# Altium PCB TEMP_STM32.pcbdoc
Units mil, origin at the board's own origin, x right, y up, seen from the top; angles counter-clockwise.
Board outline 2892.2 x 2755.09 mil, 2 copper layers (Top Layer, Bottom Layer); 81 components, 62 nets, 281 pads, 162 vias.
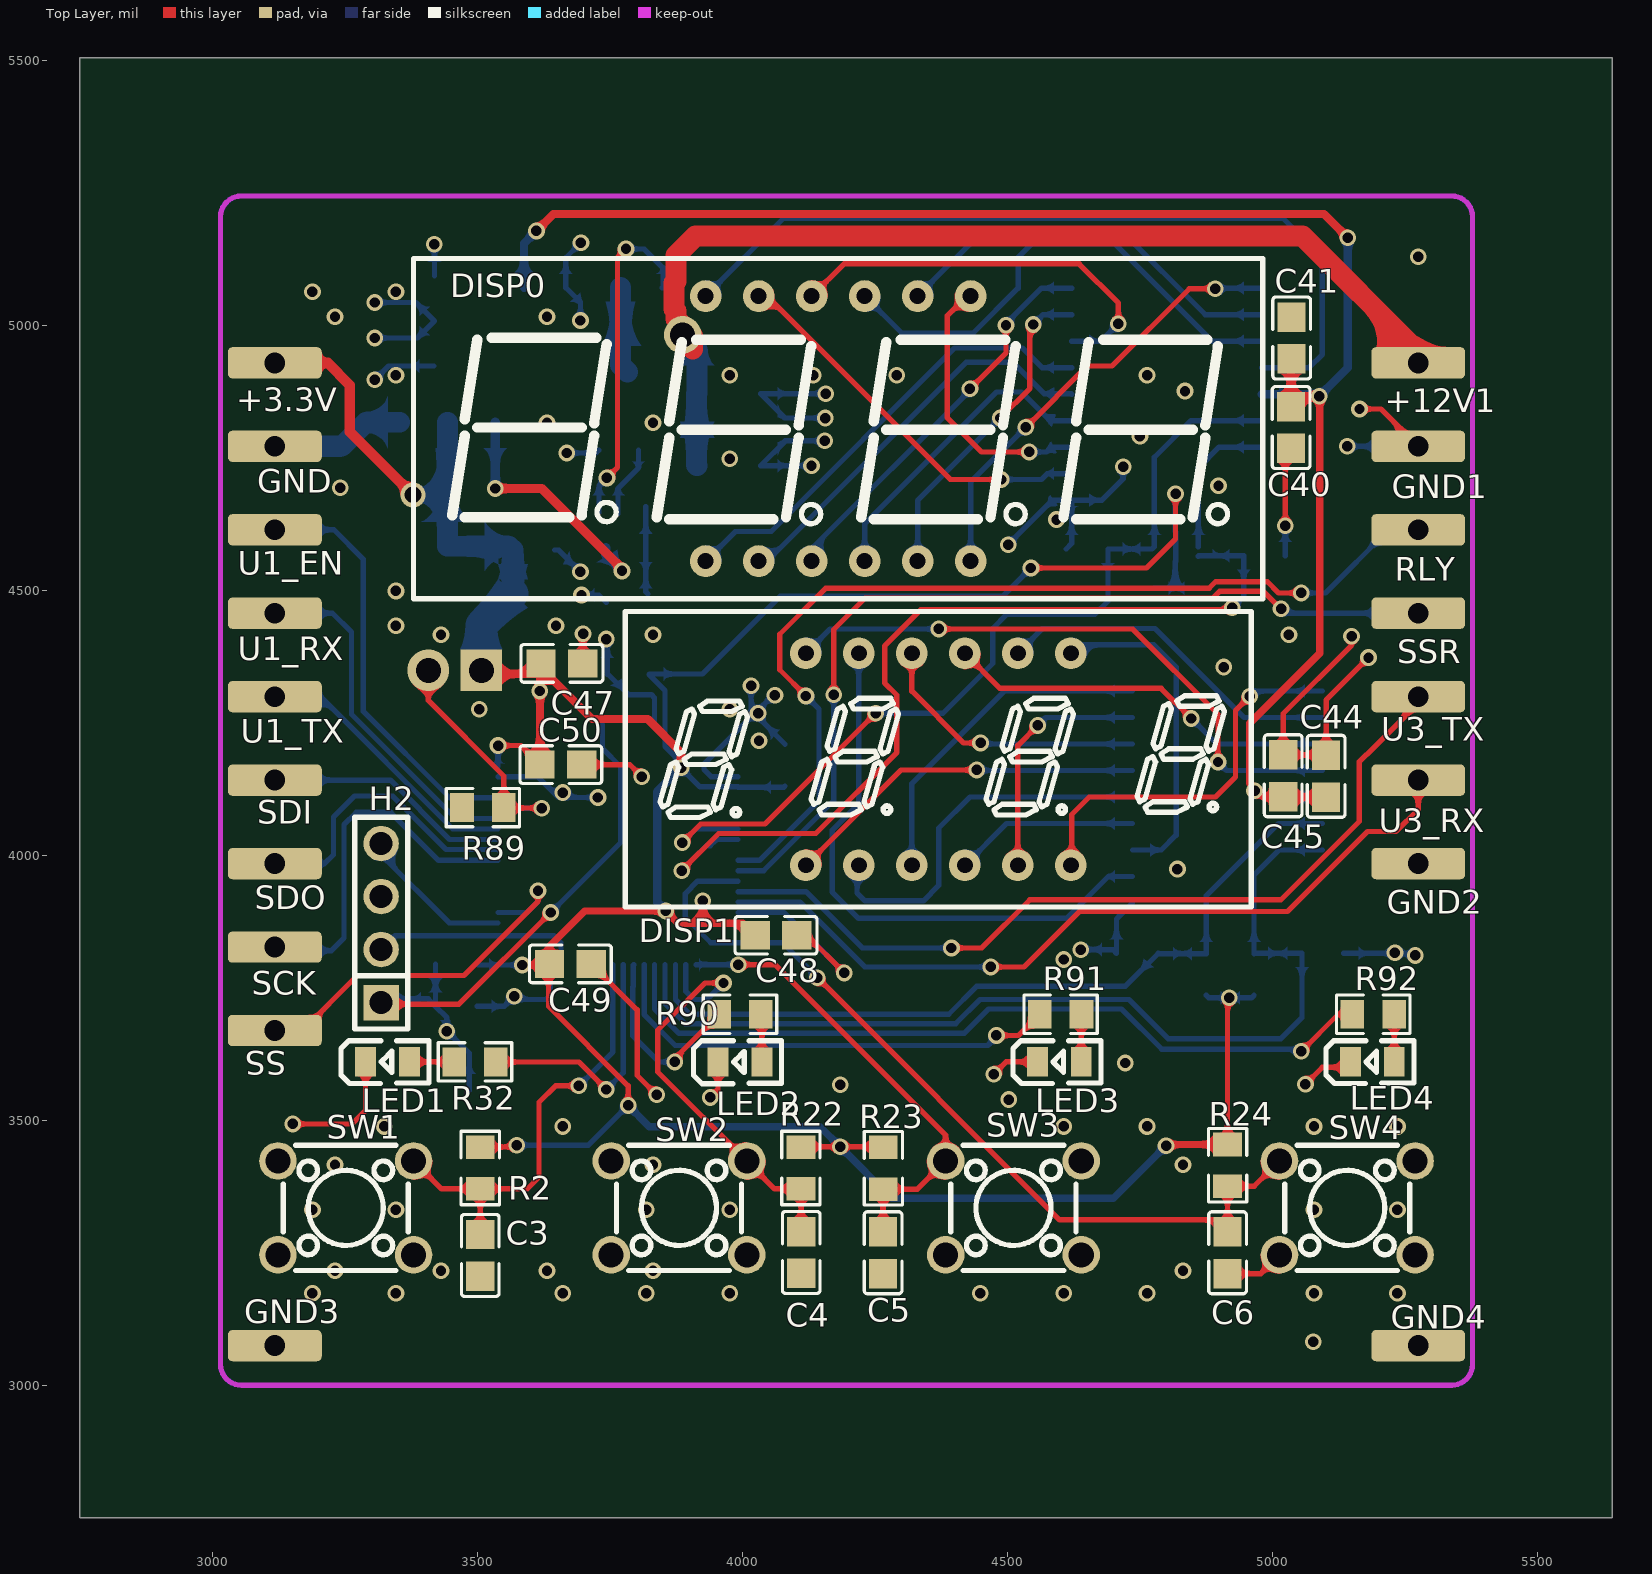
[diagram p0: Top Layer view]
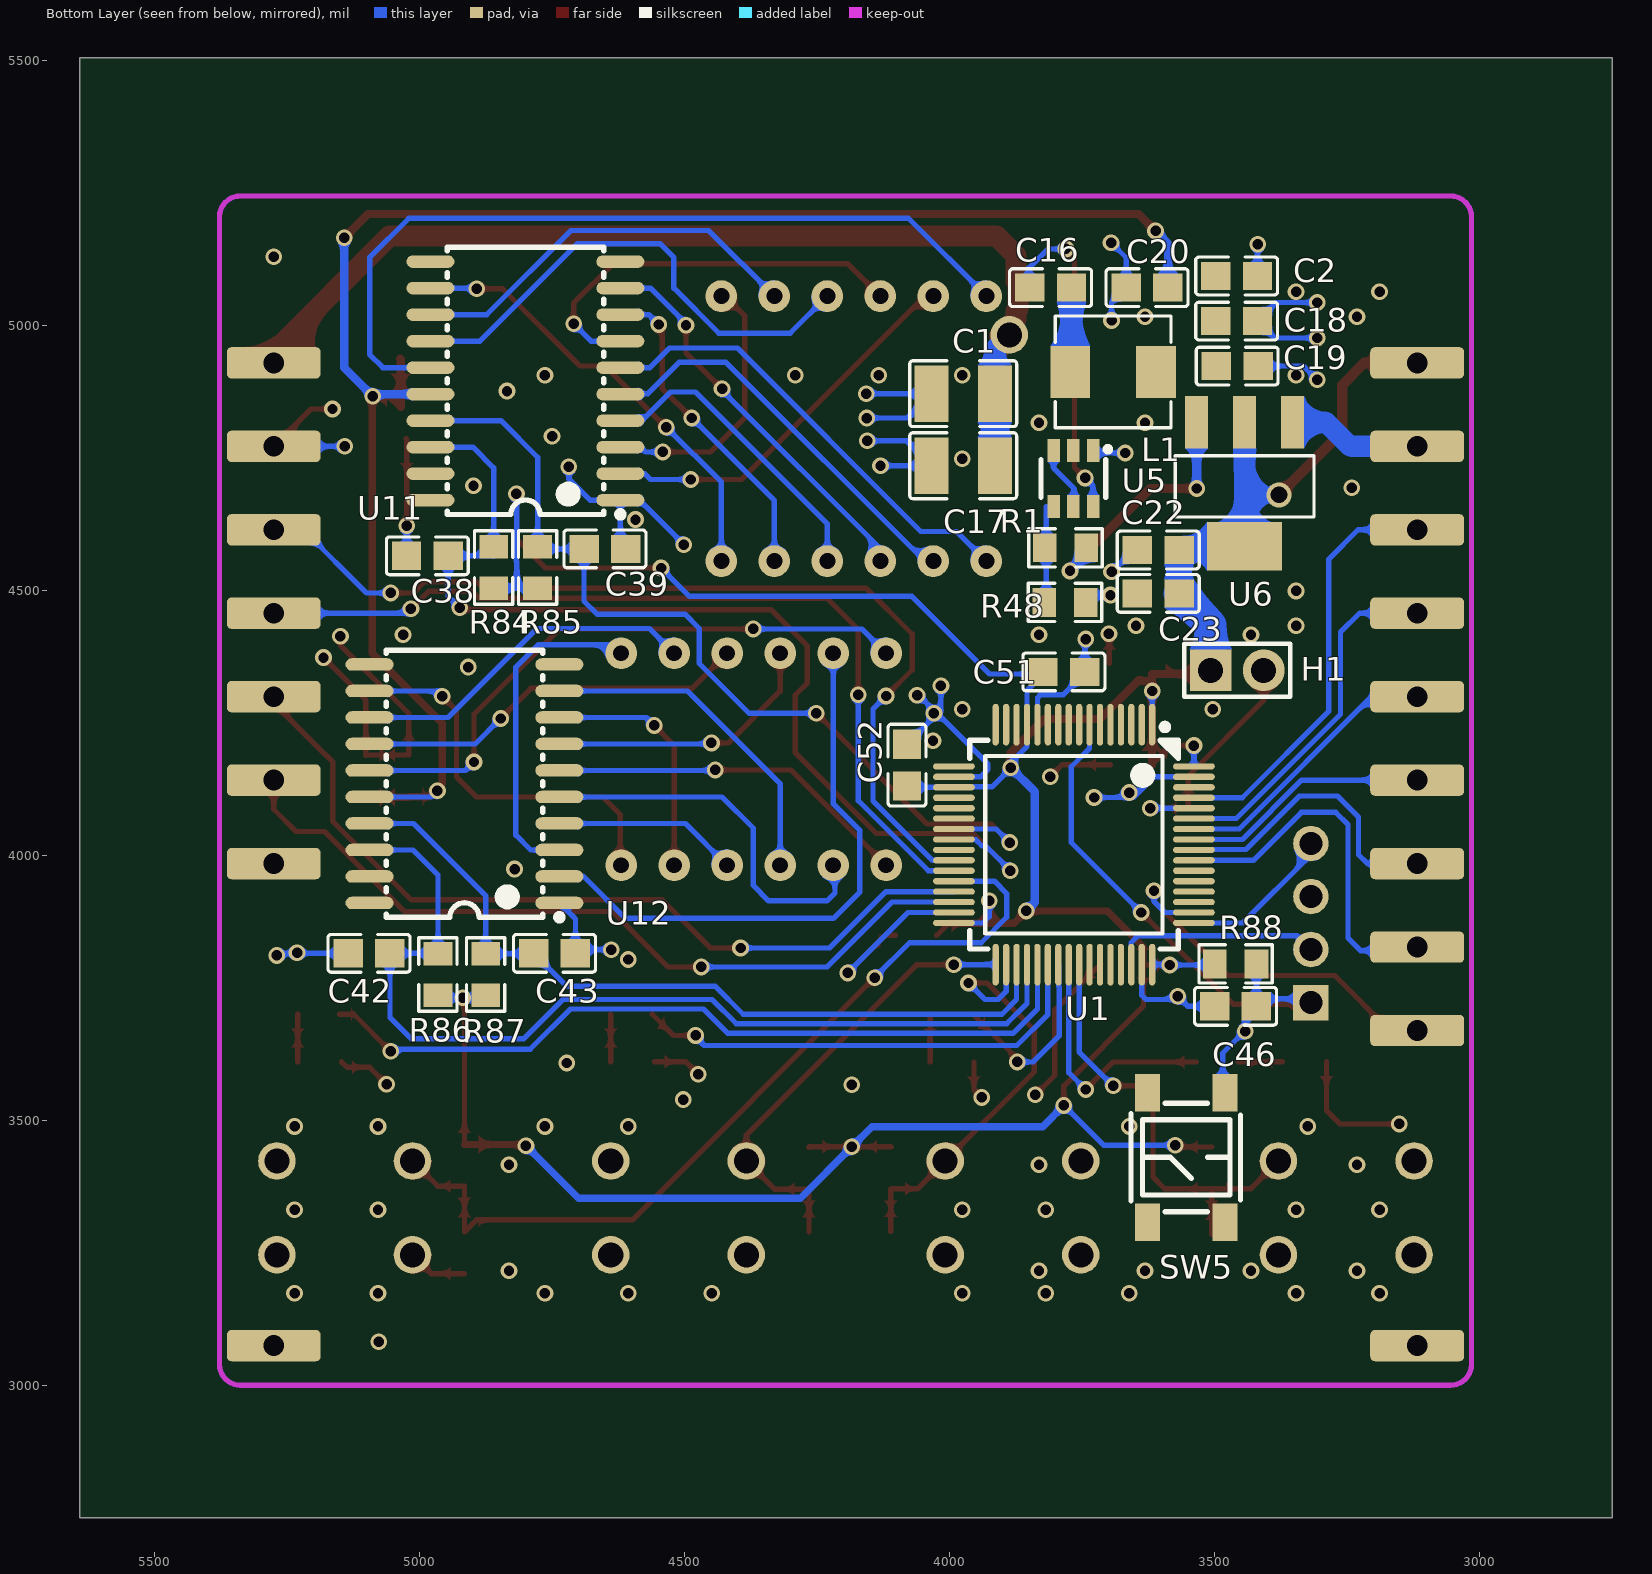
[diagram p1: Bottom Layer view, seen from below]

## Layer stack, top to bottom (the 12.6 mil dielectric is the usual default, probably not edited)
Top Layer: signal copper (thickness not stored)
Dielectric: dielectric 12.6, FR-4, Dk 4.8
Bottom Layer: signal copper (thickness not stored)

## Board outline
5642.2,2750 2750,2750 2750,5505.09 5642.2,5505.09

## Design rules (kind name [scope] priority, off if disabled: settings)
BoardOutlineClearance copperThickness1oz [All] p0: genericclearance=10 ignorepadtopadclearanceinfootprint=FALSE except(0: Arc-SplitContinuation Track-SplitContinuation SMDPad-SplitContinuation THPad-SplitContinuation Via-SplitContinuation Fill-SplitContinuation Poly-SplitContinuation Region-SplitContinuation Text-SplitContinuation; 8: Track-CutoutEdge SMDPad-CutoutEdge THPad-CutoutEdge Via-CutoutEdge Region-CutoutEdge; 11.8: Track-OutlineEdge SMDPad-OutlineEdge THPad-OutlineEdge Via-OutlineEdge Fill-OutlineEdge Region-OutlineEdge Poly-OutlineEdge Text-OutlineEdge Fill-CutoutEdge)
BoardOutlineClearance copperThickness2oz [All] p0: genericclearance=10 ignorepadtopadclearanceinfootprint=FALSE except(0: Arc-SplitContinuation Track-SplitContinuation SMDPad-SplitContinuation THPad-SplitContinuation Via-SplitContinuation Fill-SplitContinuation Poly-SplitContinuation Region-SplitContinuation Text-SplitContinuation; 6: Track-CutoutEdge SMDPad-CutoutEdge THPad-CutoutEdge Via-CutoutEdge Region-CutoutEdge; 11.8: Track-OutlineEdge SMDPad-OutlineEdge THPad-OutlineEdge Via-OutlineEdge Fill-OutlineEdge Region-OutlineEdge Poly-OutlineEdge Text-OutlineEdge Fill-CutoutEdge)
Clearance copperThickness1oz [(InNet('+12V') OR InNet('GND') OR InNet('+5V') OR InNet('$1N5723') OR InNet('$1N5726') OR InNet('+3.3V') OR InNet('CLK1') OR InNet('DIO1') OR InNet('RST') OR InNet('SEG_E2') OR InNet('SEG_D2') OR InNet('SEG_H2') OR InNet('SEG_C2') OR InNet('SEG_G2') OR InNet('DIG_8') OR InNet('SEG_B2') OR InNet('DIG_7') OR InNet('DIG_6') OR InNet('SEG_F2') OR InNet('SEG_A2') OR InNet('DIG_5') OR InNet('DIG_1') OR InNet('DIG_2') OR InNet('DIG_3') OR InNet('DIG_4') OR InNet('$1N5728') OR InNet('SWCLK') OR InNet('SWDIO') OR InNet('SEG_A1') OR InNet('SEG_B1') OR InNet('SEG_C1') OR InNet('SEG_D1') OR InNet('SEG_E1') OR InNet('SEG_F1') OR InNet('SEG_G1') OR InNet('SEG_H1') OR InNet('$1N10529') OR InNet('$1N10623') OR InNet('$1N10717') OR InNet('$1N10811') OR InNet('CLK2') OR InNet('DIO2') OR InNet('BOOT0') OR InNet('M_SCK') OR InNet('M_SS') OR InNet('U1_RX') OR InNet('U1_TX') OR InNet('U3_RX') OR InNet('U3_TX') OR InNet('M_SDI') OR InNet('M_SDO') OR InNet('LD3') OR InNet('LD2') OR InNet('LD1') OR InNet('LD4') OR InNet('SSR') OR InNet('RLY') OR InNet('U1_EN') OR InNet('SW1') OR InNet('SW2') OR InNet('SW3') OR InNet('SW4'))] p1: gap=7 ignorepadtopadclearanceinfootprint=FALSE except(7.9: SMDPad-SMDPad; 8: Track-Track Track-SMDPad Track-Via SMDPad-Via THPad-Via SMDPad-Fill THPad-Fill Via-Fill Fill-Fill Track-Region SMDPad-Region THPad-Region Via-Region Region-Region Track-Poly SMDPad-Poly THPad-Poly Via-Poly Fill-Poly Region-Poly Poly-Poly Track-Text SMDPad-Text THPad-Text Via-Text Fill-Text Region-Text Poly-Text Text-Text Track-Hole SMDPad-Hole THPad-Hole Via-Hole Fill-Hole Region-Hole Poly-Hole Text-Hole Sheet-Hole; 10: Track-THPad SMDPad-THPad THPad-THPad; 11.8: Track-Fill Fill-Region Track-Sheet SMDPad-Sheet THPad-Sheet Via-Sheet Fill-Sheet Region-Sheet Poly-Sheet Text-Sheet; 12: Via-Via)
Clearance copperThickness2oz [All] p1: gap=7 ignorepadtopadclearanceinfootprint=FALSE except(6: Track-SMDPad SMDPad-SMDPad Track-THPad SMDPad-THPad THPad-THPad Track-Via SMDPad-Via THPad-Via Via-Via SMDPad-Fill THPad-Fill Via-Fill Fill-Fill Track-Region SMDPad-Region THPad-Region Via-Region Region-Region Track-Poly SMDPad-Poly THPad-Poly Via-Poly Fill-Poly Region-Poly Poly-Poly Track-Text SMDPad-Text THPad-Text Via-Text Fill-Text Region-Text Poly-Text Text-Text; 6.9: Track-Hole SMDPad-Hole THPad-Hole Via-Hole Fill-Hole Region-Hole Poly-Hole Text-Hole Sheet-Hole; 8: Track-Track; 11.8: Track-Fill Fill-Region Track-Sheet SMDPad-Sheet THPad-Sheet Via-Sheet Fill-Sheet Region-Sheet Poly-Sheet Text-Sheet)
DiffPairsRouting differentialPair [All] p1: maxuncoupledlength=10 minlimit=5.9843 maxlimit=5.9843 mostfreqgap=5.9843 toplayer_minwidth=5 toplayer_prefwidth=10 toplayer_maxwidth=100 bottomlayer_minwidth=5 bottomlayer_prefwidth=10 bottomlayer_maxwidth=100
PasteMaskExpansion pasteMaskExpansion [All] p1: expansion=0
PlaneConnect innerPlane [All] p1: planeconnectstyle=Relief reliefexpansion=20 reliefentries=4 reliefconductorwidth=10 reliefairgap=10
PolygonConnect copperRegion [All] p1: connectstyle=Direct reliefentries=4 reliefconductorwidth=10 polygonreliefangle="90 Angle" airgapwidth=10
RoutingVias viaSize [All] p1: viastyle="Through Hole" holewidth=19.685 minholewidth=19.685 maxholewidth=393.7008 width=31.496 minwidth=19.685 maxwidth=393.7008
SolderMaskExpansion solderMaskExpansion [All] p1: useseparateexpansions=TRUE expansion=2.0079 expansionbottom=2.0079
Width copperThickness1oz [All] p1: maxlimit=100 minlimit=5 preferedwidth=10
Width copperThickness2oz [All] p1: maxlimit=100 minlimit=8 preferedwidth=10

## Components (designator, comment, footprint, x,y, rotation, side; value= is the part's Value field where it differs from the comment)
+3.3V "S_TM" S_FT 3118.36,4929.13 r90 top
+12V1 "S_TM" S_FT 5275.84,4929.13 r90 top
C1 "CS3225X7R106K500NRL" C1210 3975,4871 r180 bottom
C2 "GRM21BZ71A226ME15L" C0805 3459,5093 r0 bottom
C3 "CC0805KRX7R9BB104" C0805 3506,3245 r90 top
C4 "CC0805KRX7R9BB104" C0805 4111.63,3250.63 r90 top
C5 "CC0805KRX7R9BB104" C0805 4266,3250 r90 top
C6 "CC0805KRX7R9BB104" C0805 4916,3250 r90 top
C16 "CC0805KRX7R9BB104" C0805 3810,5071 r180 bottom
C17 "CS3225X7R106K500NRL" C1210 3975,4735 r180 bottom
C18 "GRM21BZ71A226ME15L" C0805 3459,5008 r0 bottom
C19 "GRM21BZ71A226ME15L" C0805 3458,4923 r0 bottom
C20 "CC0805KRX7R9BB104" C0805 3628,5071 r180 bottom
C22 "CC0805KRX7R9BB104" C0805 3607,4576 r180 bottom
C23 "GRM21BR61C106KE15L" C0805 3607,4494 r180 bottom
C38 "CC0805KRX7R9BB101" C0805 4986,4565 r180 bottom
C39 "CC0805KRX7R9BB101" C0805 4651,4578 r0 bottom
C40 "GRM21BZ71A226ME15L" C0805 5036,4807 r90 top
C41 "CC0805KRX7R9BB104" C0805 5037,4976 r270 top
C42 "CC0805KRX7R9BB101" C0805 5096,3815 r180 bottom
C43 "CC0805KRX7R9BB101" C0805 4746,3815 r0 bottom
C44 "GRM21BZ71A226ME15L" C0805 5102,4149 r270 top
C45 "CC0805KRX7R9BB104" C0805 5021,4150 r270 top
C46 "CC0805KRX7R9BB104" C0805 3461,3715 r180 bottom
C47 "CC0805KRX7R9BB101" C0805 3660,4362 r180 top
C48 "CC0805KRX7R9BB101" C0805 4064,3849 r180 top
C49 "CC0805KRX7R9BB101" C0805 3676,3795 r180 top
C50 "CC0805KRX7R9BB101" C0805 3658,4171 r180 top
C51 "CC0805KRX7R9BB101" C0805 3785,4346 r0 bottom
C52 "CC0805KRX7R9BB101" C0805 4081,4170 r270 bottom
DISP0 "FJ4401BH" LED-SEG-TH_12P-L40.4-W16.0-P2.54-S12.70-BL 4181.35,4805.12 r0 top locked
DISP1 "FJ3461BH" LED-SEG-TH_12P-L30.0-W13.7-P2.54-S10.16-BL 4370.33,4181.1 r0 top locked
GND "S_TM" S_FT 3118.36,4771.65 r270 top
GND1 "S_TM" S_FT 5275.84,4771.65 r90 top
GND2 "S_TM" S_FT 5275.84,3984.25 r90 top
GND3 "S_TM" S_FT 3118.36,3074.8 r270 top
GND4 "S_TM" S_FT 5275.84,3074.8 r90 top
H1 "PZ254V-11-02P" HDR-TH_2P-P2.54-V-M 3458,4349 r180 bottom
H2 "PZ254V-11-04P" HDR-TH_4P-P2.54-V-M 3319,3872 r90 top
L1 "RS0530-3R3MS" IND-SMD_L5.4-W5.2_RS0530 3692,4912 r0 bottom
LED1 "XL-2012SURC" LED0805-R-RD 3330.96,3610.24 r0 top
LED2 "XL-2012SURC" LED0805-R-RD 3996,3610 r0 top
LED3 "XL-2012SURC" LED0805-R-RD 4598.68,3610.24 r0 top
LED4 "XL-2012SURC" LED0805-R-RD 5189.23,3610.24 r0 top
R1 "RC0805FR-0756K2L" R0805 3782,4580 r0 bottom
R2 "RC0805FR-0710KL" R0805 3506,3410 r90 top
R22 "RC0805FR-0710KL" R0805 4111,3410 r90 top
R23 "RC0805FR-0710KL" R0805 4266.63,3409.37 r90 top
R24 "RC0805FR-0710KL" R0805 4916,3415 r90 top
R32 "RC0805FR-071KL" R0805 3496,3610 r0 top
R48 "RC0805FR-0710KL" R0805 3783,4477 r0 bottom
R84 "RC0805FR-0710KL" R0805 4861,4543 r270 bottom
R85 "RC0805FR-0710KL" R0805 4778,4543 r270 bottom
R86 "RC0805FR-0710KL" R0805 4966,3775 r270 bottom
R87 "RC0805FR-0710KL" R0805 4876,3775 r270 bottom
R88 "RC0805FR-0710KL" R0805 3461,3795 r0 bottom
R89 "RC0805FR-0710KL" R0805 3511,4090 r0 top
R90 "RC0805FR-071KL" R0805 3996,3700 r180 top
R91 "RC0805FR-071KL" R0805 4601,3700 r180 top
R92 "RC0805FR-071KL" R0805 5191,3700 r180 top
RLY "S_TM" S_FT 5275.84,4614.17 r90 top
SCK "S_TM" S_FT 3118.36,3826.77 r270 top
SDI "S_TM" S_FT 3118.36,4141.73 r90 top
SDO "S_TM" S_FT 3118.36,3984.25 r90 top
SS "S_TM" S_FT 3118.36,3669.29 r90 top
SSR "S_TM" S_FT 5275.84,4456.69 r90 top
SW1 "YTS1R0011FBT00" SW-TH_4P-L6.0-W6.0-P4.50-LS6.5 3252.22,3334.65 r0 top
SW2 "YTS1R0011FBT00" SW-TH_4P-L6.0-W6.0-P4.50-LS6.5 3881,3334.65 r0 top
SW3 "YTS1R0011FBT00" SW-TH_4P-L6.0-W6.0-P4.50-LS6.5 4512.06,3334.65 r0 top
SW4 "YTS1R0011FBT00" SW-TH_4P-L6.0-W6.0-P4.50-LS6.5 5141.98,3334.65 r0 top
SW5 "TSC005A1618A03" KEY-SMD_4P-L5.2-W5.2-P3.70-LS6.4 3554.04,3430 r270 bottom
U1 "STM32F103RCT6" LQFP-64_L10.0-W10.0-P0.50-LS12.0-BL 3766,4020 r0 bottom locked
U1_EN "S_TM" S_FT 3118.36,4614.17 r90 top
U1_RX "S_TM" S_FT 3118.36,4456.69 r90 top
U1_TX "S_TM" S_FT 3118.36,4299.21 r90 top
U3_RX "S_TM" S_FT 5275.84,4141.73 r90 top
U3_TX "S_TM" S_FT 5275.84,4299.21 r90 top
U5 "TPS562208DDCR" SOT-23-6_L2.9-W1.6-P0.95-LS2.8-BR 3767,4711 r90 bottom
U6 "AMS1117-3.3_C6068481" SOT-223-3_L6.5-W3.4-P2.30-LS7.0-BR 3444,4700 r90 bottom
U11 "TM1637" SOP-20_L12.8-W7.5-P1.27-LS10.4-BL 4801,4895 r90 bottom
U12 "TM1637" SOP-20_L12.8-W7.5-P1.27-LS10.4-BL 4916,4135 r90 bottom locked

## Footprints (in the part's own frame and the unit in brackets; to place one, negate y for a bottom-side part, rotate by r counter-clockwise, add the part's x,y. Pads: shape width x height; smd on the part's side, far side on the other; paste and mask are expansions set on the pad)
C0805 [mm]
  rect 1.41x1.35 smd: 1(-1,0) 2(1,0)
  silkscreen extent -1.96,-0.9 1.96,0.9
C1210 [mm]
  rect 1.635x2.7 smd: 1(-1.517,0) 2(1.517,0)
  silkscreen extent -2.56,-1.58 2.56,1.58
HDR-TH_2P-P2.54-V-M [mm]
  rect 2x2 hole 1.2: 1(-1.27,0)
  round 2 hole 1.2: 2(1.27,0)
  silkscreen extent -2.54,-1.27 2.54,1.27
HDR-TH_4P-P2.54-V-M [mm]
  rect 1.7x1.7 hole 1.1: 1(-3.81,0)
  round 1.7 hole 1.1: 2(-1.27,0) 3(1.27,0) 4(3.81,0)
  silkscreen extent -5.08,-1.27 5.08,1.27
IND-SMD_L5.4-W5.2_RS0530 [mm]
  rect 1.9x2.5 smd: 1(2.05,0) 2(-2.05,0)
  silkscreen extent -2.78,-2.68 2.78,2.68
KEY-SMD_4P-L5.2-W5.2-P3.70-LS6.4 [mm]
  rect 1.8x1.2 smd: 1(-3.1,1.85) 2(3.1,1.85) 3(-3.1,-1.85) 4(3.1,-1.85)
  silkscreen extent -2.6,-2.65 2.6,2.6
LED0805-R-RD [mm]
  rect 1x1.4 smd: 1(1.05,0) 2(-1.05,0)
  silkscreen extent -2.22,-1.04 1.99,1.01
LED-SEG-TH_12P-L30.0-W13.7-P2.54-S10.16-BL [mil]
  round 60 hole 30: 1(-250,-200) 2(-150,-200) 3(-50,-200) 4(50,-200) 5(150,-200) 6(250,-200) 7(250,200) 8(150,200) 9(50,200) 10(-50,200) 11(-150,200) 12(-250,200)
  silkscreen extent -591,-279 591,279
LED-SEG-TH_12P-L40.4-W16.0-P2.54-S12.70-BL [mil]
  round 60 hole 30: 1(-250,-250) 2(-150,-250) 3(-50,-250) 4(50,-250) 5(150,-250) 6(250,-250) 7(250,250) 8(150,250) 9(50,250) 10(-50,250) 11(-150,250) 12(-250,250)
  silkscreen extent -801,-321 801,321
LQFP-64_L10.0-W10.0-P0.50-LS12.0-BL [mm]
  oval 0.3x2 smd: 1(-3.75,-5.75) 2(-3.25,-5.75) 3(-2.75,-5.75) 4(-2.25,-5.75) 5(-1.75,-5.75) 6(-1.25,-5.75) 7(-0.75,-5.75) 8(-0.25,-5.75) 9(0.25,-5.75) 10(0.75,-5.75) 11(1.25,-5.75) 12(1.75,-5.75) 13(2.25,-5.75) 14(2.75,-5.75) 15(3.25,-5.75) 16(3.75,-5.75) 33(3.75,5.75) 34(3.25,5.75) 35(2.75,5.75) 36(2.25,5.75) 37(1.75,5.75) 38(1.25,5.75) 39(0.75,5.75) 40(0.25,5.75) 41(-0.25,5.75) 42(-0.75,5.75) 43(-1.25,5.75) 44(-1.75,5.75) 45(-2.25,5.75) 46(-2.75,5.75) 47(-3.25,5.75) 48(-3.75,5.75)
  oval 2x0.3 smd: 17(5.75,-3.75) 18(5.75,-3.25) 19(5.75,-2.75) 20(5.75,-2.25) 21(5.75,-1.75) 22(5.75,-1.25) 23(5.75,-0.75) 24(5.75,-0.25) 25(5.75,0.25) 26(5.75,0.75) 27(5.75,1.25) 28(5.75,1.75) 29(5.75,2.25) 30(5.75,2.75) 31(5.75,3.25) 32(5.75,3.75) 49(-5.75,3.75) 50(-5.75,3.25) 51(-5.75,2.75) 52(-5.75,2.25) 53(-5.75,1.75) 54(-5.75,1.25) 55(-5.75,0.75) 56(-5.75,0.25) 57(-5.75,-0.25) 58(-5.75,-0.75) 59(-5.75,-1.25) 60(-5.75,-1.75) 61(-5.75,-2.25) 62(-5.75,-2.75) 63(-5.75,-3.25) 64(-5.75,-3.75)
  silkscreen extent -5,-5.79 5,5
R0805 [mm]
  rect 1.133x1.377 smd: 1(-1,0) 2(1,0)
  silkscreen extent -1.76,-0.92 1.76,0.92
S_FT [mm]
  rrect30% 1.5x4.5 hole 1: 1(0,0)
SOP-20_L12.8-W7.5-P1.27-LS10.4-BL [mm]
  oval 0.6x2.3 smd: 1(-5.715,-4.55) 2(-4.445,-4.55) 3(-3.175,-4.55) 4(-1.905,-4.55) 5(-0.635,-4.55) 6(0.635,-4.55) 7(1.905,-4.55) 8(3.175,-4.55) 9(4.445,-4.55) 10(5.715,-4.55) 11(5.715,4.55) 12(4.445,4.55) 13(3.175,4.55) 14(1.905,4.55) 15(0.635,4.55) 16(-0.635,4.55) 17(-1.905,4.55) 18(-3.175,4.55) 19(-4.445,4.55) 20(-5.715,4.55)
  silkscreen extent -6.55,-4.7 6.4,3.75
SOT-23-6_L2.9-W1.6-P0.95-LS2.8-BR [mm]
  rect 1.1x0.6 smd: 1(1.35,-0.95) 2(1.35,0) 3(1.35,0.95) 4(-1.35,0.95) 5(-1.35,0) 6(-1.35,-0.95)
  silkscreen extent -0.9,-1.78 1.52,1.55
SOT-223-3_L6.5-W3.4-P2.30-LS7.0-BR [mm]
  rect 2.5x1.1 smd: 1(2.97,-2.3) 2(2.97,0) 3(2.97,2.3)
  rect 2.34x3.6 smd: 4(-2.97,0)
  silkscreen extent -1.57,-3.33 1.37,3.33
SW-TH_4P-L6.0-W6.0-P4.50-LS6.5 [mm]
  round 1.8 hole 1.2: 1(-3.25,2.25) 2(3.25,2.25) 3(-3.25,-2.25) 4(3.25,-2.25)
  silkscreen extent -3,-3 3,3

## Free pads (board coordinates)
  round 70.87 hole 47.24: 1(3888,4982)

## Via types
v1: diameter 31.5, hole 19.68, Top Layer to Bottom Layer, 113 vias
v2: diameter 31.5, hole 19.7, Top Layer to Bottom Layer, 48 vias
v3: diameter 47.24, hole 31.5, Top Layer to Bottom Layer, 1 vias

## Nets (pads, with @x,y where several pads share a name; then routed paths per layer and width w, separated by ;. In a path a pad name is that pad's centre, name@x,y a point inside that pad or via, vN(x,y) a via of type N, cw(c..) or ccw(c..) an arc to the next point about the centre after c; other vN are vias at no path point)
$1N5723: C16.2 L1.1 U5.2 | length 164.4
  Bottom Layer w39.37: C16.2 3770.63,4925.08 L1.1@3783.71,4912
$1N5726: C16.1 U5.6 | length 642.2
  Top Layer w10: v2(3745,4712) 3765,4732 3765,5128 v2(3781,5144)
  Bottom Layer w10: U5.6@3730,4645.66 3730,4697 v2(3745,4712) ; v2(3781,5144) 3815.32,5144 3851,5108.31 3851,5072.63 C16.1
$1N5728: R1.2 R48.2 U5.4 | length 166.5
  Bottom Layer w10: 3818.4,4657.85 3818.4,4496.97 R48.2@3822.37,4493
$1N10529: LED1.1 R32.1 | length 84.4
  Top Layer w10: LED1.1 3456.39,3610.24 R32.1
$1N10623: LED2.1 R90.1 | length 90.8
  Top Layer w10: R90.1 4037.35,3698.02 LED2.1
$1N10717: LED3.1 R91.1 | length 89.9
  Top Layer w10: LED3.1 4640.03,3699.66 R91.1
$1N10811: LED4.1 R92.1 | length 89.9
  Top Layer w10: R92.1 5230.58,3699.79 LED4.1
+3.3V: +3.3V.1 C22.2 C23.2 C47.2 C48.2 C49.2 C50.2 C51.2 C52.2 H1.1 R2.2 R22.2 R23.2 R24.2 R84.2 R85.2 R86.2 R87.2 R88.2 U1.1 U1.13 U1.19 U1.32 U1.48 U1.64 U6.2 U6.4 | length 7281.4
  Top Layer w10: R2.2 3571.37,3449.37 v1(3575,3453) ; v1(3539.63,4207) 3582.63,4207 C50.2 ; v1(3585,3793) C49.2@3634.63,3793 ; C49.2 C49.2@3634.63,3793 ; v1(3785,3528) 3785,3565 3634.63,3715.37 C49.2@3634.63,3793 ; 3926,3872 v1(3926,3914) ; C48.2@4001.63,3872 C48.2 ; R22.2 4111.63,3450 v1(4185,3450) 4265.37,3450 R23.2 ; v2(4545,4542) 4763,4542 4818,4597 v2(4818,4682) ; R24.2 4916,3728 v2(4919,3731)
  Top Layer w13.78: C49.2 3636,3795.63 3636,3828 3703,3895 v1(3856,3895) 3879,3872 3926,3872 C48.2@4001.63,3872 ; v1(4800,3452) 4802.37,3454.37 R24.2
  Top Layer w15.75: H1.1 3515,4342 3618.63,4342 3618.63,4328.79 ; C50.2 3618.63,4309.37 v1(3618,4310) 3618.63,4310.63 3618.63,4328.79 ; v1(3885,4165) 3885,4194 3822,4257 3717,4257 3644,4330 3640,4330 3638.79,4328.79 3618.63,4328.79
  Top Layer w19.68: +3.3V.1 3217.87,4929.13 3260,4887 3260,4799.07 v3(3379,4680.07)
  Bottom Layer w10: R88.2 3502.37,3793 v1(3585,3793) 3585.63,3793.63 U1.48 ; U1.64 v1(3539.63,4207) ; v1(3575,3453) 3710,3453 v1(3785,3528) ; v1(3618,4310) 3618.36,4309.64 U1.1 ; v1(3926,3914) 3926,3884 3937.64,3872.36 U1.32 ; C52.2 4078.64,4128.27 U1.19 3991.59,4129.05 3920.95,4129.05 v1(3885,4165) 3885,4175 3854.58,4205.42 U1.13 3854.58,4310.75 3824.24,4341.09 3825.24,4342.09 3925.09,4342.09 4071.51,4488.51 4491.51,4488.51 v2(4545,4542) ; R85.2 4817.13,4503.63 ; v2(4818,4682) 4817.13,4681.13 4817.13,4611.02 4818.11,4610.05 4818.11,4554.69 4817.13,4553.72 4817.13,4503.63 ; R84.2 4817.13,4503.63 ; R87.2 4880.63,3731 v2(4919,3731) 4961.37,3731 R86.2
  Bottom Layer w13.78: v1(3785,3528) 3825,3488 4147,3488 v1(4185,3450) 4282,3353 4701,3353 v1(4800,3452)
  Bottom Layer w15.75: v1(3856,3895) 3840,3911 3840,4120 v1(3885,4165)
  Bottom Layer w19.68: v3(3379,4680.07) 3437.42,4680.07 3444,4673.49
  Bottom Layer w39.37: U6.2 3444,4673.49 U6.4 3560.56,4583.07 C22.2 C23.2
  Bottom Layer w59.06: H1.1 3508,4434.37 C23.2
+5V: C2.2 C18.2 C19.2 C20.2 C40.2 C41.2 C44.2 C45.2 L1.2 R1.1 U6.3 U11.16 U12.16 | length 3816
  Top Layer w10: v2(4967,4121.5) v2@4967,4127
  Top Layer w13.78: v2@5090,4854 5090,4381 4958,4249 4958,4136 4967,4127 4983.37,4110.63 C45.2 5022,4109.63 C44.2
  Top Layer w15.75: v2(3612,5178) 3644,5210 5098,5210 v2(5143,5165) ; C41.2 ccw(c5039.41,4934.22) 5036,4934.22 C40.2 5055.63,4866 v2(5089,4866)
  Top Layer w17.72: v2(3534.55,4692) 3622,4692 3773.5,4540.5 v2(3773.5,4536.5)
  Bottom Layer w10: v2(4967,4121.5) 4978.5,4110 U12.16
  Bottom Layer w15.75: C20.2 3588.63,5154.63 v2(3612,5178) ; U11.16 5085,4870 v2(5089,4866) 5143,4920 v2(5143,5165)
  Bottom Layer w17.72: v2(3534.55,4692) U6.3 ; R1.1 3742.63,4567.37 v2(3773.5,4536.5)
+12V: +12V1.1 C1.2 C17.2 pad.1 U5.3 U5.5 | length 2114.8
  Top Layer w39.37: pad.1@3907,4955 3907,4980 3875,5012 3875,5027.06 3871.67,5030.4 3871.67,5079.84 3875,5083.17 3875,5131.63 3911.82,5168.45 5057.53,5168.45 5275.84,4950.13 +12V1.1
  Bottom Layer w10: U5.5@3766,4644.26 3766,4692.34 3804.4,4730.74 U5.3
  Bottom Layer w39.37: pad.1 3915.26,4954.74 C1.2 ; C1.2@3914,4871 3914,4736.26 C17.2
BOOT0: H1.2 R89.2 U1.60 | length 472.4
  Top Layer w10: H1.2 3408,4292 3550.37,4149.63 R89.2 3551.37,4089 v1(3622,4089)
  Bottom Layer w10: U1.60 3621.9,4088.9 v1(3622,4089)
CLK1: C38.2 R84.1 U1.24 U11.18 | length 2002.2
  Top Layer w10: v1(3886,3971) 3956,4041 4139,4041 4292,4194 4292,4302 4269,4325 4269,4395 4337,4463 4921,4463 v1(4925,4467)
  Bottom Layer w10: v1(3886,3971) 3932.99,4017.99 3940.01,4017.99 3951.08,4029.06 3952.06,4029.06 3952.84,4029.84 U1.24 ; R84.1@4861,4564.37 4861.63,4565 C38.2 4946.63,4488.63 v1(4925,4467) ; R84.1 4861,4731 4900,4770 U11.18
CLK2: C42.2 R86.1 U1.36 U12.18 | length 1866.8
  Bottom Layer w10: U1.36 3854.58,3720.42 3893,3682 4403,3682 4449,3728 4730,3728 4804,3654 5017,3654 5056.63,3693.63 C42.2 4966.63,3815 R86.1 4966,3963 5013,4010 U12.18
DIG_1: DISP0.12 U11.15 | length 1563.4
  Bottom Layer w10: DISP0.12 4078.24,5202 5021,5202 5095,5128 5095,4945 5070,4920 U11.15
DIG_2: DISP0.9 U11.14 | length 958
  Bottom Layer w10: DISP0.9 4301.47,4985 4436,4985 4521,5070 4521,5128 4547,5154 4703,5154 4887,4970 U11.14
DIG_3: DISP0.8 U11.13 | length 765.9
  Bottom Layer w10: DISP0.8 4455.24,5179 4715,5179 4874,5020 U11.13
DIG_4: DISP0.6 U11.12 | length 849.5
  Top Layer w10: v1(4535.5,4807.5) 4651,4923 4698,4923 4844,5069 v1(4893,5069)
  Bottom Layer w10: DISP0.6 4431.35,4704.35 4534.5,4807.5 v1(4535.5,4807.5) ; v1(4893,5069) 4894,5070 U11.12
DIG_5: DISP1.12 U12.15 | length 1157.1
  Top Layer w10: v1(4371,4427) 4737,4427 4898,4266 v1(4898,4176)
  Bottom Layer w10: DISP1.12 4166.23,4427 v1(4371,4427) ; v1(4898,4176) 4914,4160 U12.15
DIG_6: DISP1.9 U12.14 | length 745.7
  Top Layer w10: DISP1.9 4486.43,4315 4790.74,4315 v1(4847.74,4258)
  Bottom Layer w10: v1(4847.74,4258) 4895.74,4210 U12.14
DIG_7: DISP1.8 U12.13 | length 663.8
  Bottom Layer w10: DISP1.8 4567.23,4428 4779,4428 4947,4260 U12.13
DIG_8: DISP1.6 U12.12 | length 739.5
  Top Layer w10: DISP1.6 4622,3982.77 4622,4077 4655,4110 4893,4110 4931,4148 4931,4273 v1(4958,4300)
  Bottom Layer w10: v1(4958,4300) 4968,4310 U12.12
DIO1: C39.2 R85.1 U1.23 U11.17 | length 1734.1
  Top Layer w10: v1(3887,4024) 3922,4059 4043,4059 v1(4252,4268)
  Bottom Layer w10: v1(3887,4024) 3912.53,4049.53 U1.23 ; v1(4252,4268) 4379,4268 4473,4362 4473,4428 4500,4455 4666.11,4455 4690.37,4479.26 C39.2 4773.63,4578 R85.1 4778,4751 4847,4820 U11.17
DIO2: C43.2 R87.1 U1.35 U12.17 | length 1512.1
  Bottom Layer w10: U1.35 3874.27,3727.73 3902,3700 4390,3700 4443,3753 4723.37,3753 C43.2 4786,3814.37 R87.1 4876,3924 5012,4060 U12.17
GND: C1.1 C2.1 C3.1 C4.1 C5.1 C6.1 C17.1 C18.1 C19.1 C20.1 C22.1 C23.1 C38.1 C39.1 C40.1 C41.1 C42.1 C43.1 C44.1 C45.1 C46.1 C47.1 C48.1 C49.1 C50.1 C51.1 C52.1 GND1.1 GND2.1 GND3.1 GND4.1 GND.1 H2.3 LED1.2 LED2.2 LED3.2 LED4.2 R48.1 R89.1 SW1.4 SW2.4 SW3.3 SW4.3 SW5.3 U1.12 U1.18 U1.31 U1.47 U1.63 U5.1 U6.1 U11.1 U12.1 | length 5817.6
  Top Layer w10: v2(3152,3493) 3264,3493 3289.61,3518.61 LED1.2 ; C50.1 3788,4171 v2(3811,4148) ; C47.1 3699.37,4417.37 v2(3700,4418) ; C49.1 3802,3708.37 3802,3585 v2(3839,3548) ; v2(3940,3543) 3954.65,3557.65 LED2.2 ; C48.1 4122,3849 v2(4193,3778) ; v2(4475,3587) 4498.24,3610.24 LED3.2 ; C6.1 4978.6,3210.63 SW4.3 ; v2(5025,4622) 5025,4784.63 C40.1@5026,4785.63 ; v2(5063,3568) 5095,3600 5137.64,3600 LED4.2 ; v2(5150,4413) 5150,4396 5021,4267 C45.1 5101,4189.37 C44.1 5102,4293 v2(5182,4373) ; v2(5165,4842) 5205.5,4842 GND1.1
  Bottom Layer w10: v2(3307,4897) 3333,4923 C19.1 ; v2(3307,4976) 3387.63,4976 C18.1 3384.63,5043 v2(3307,5043) ; v2(3419,5153) 3419.63,5152.37 C2.1 ; C46.1 3551,3715 v2(3570,3734) 3576,3728 3630,3728 3638.05,3736.05 U1.47 ; U1.63 3615.05,4147.95 3654,4109 v2(3728,4109) ; C22.1 3654,4576 v2(3695,4535) ; v2(3669,4759) 3724.45,4759 U5.1 ; v2(3695,5009) 3695,5043.37 C20.1 3667.37,5127.37 v2(3696,5156) ; v2(3697,4491) 3729.63,4491 R48.1 ; v2(3744,4408) 3745.63,4406.37 C51.1 ; C51.1@3745.5,4341.09 C51.1@3745.63,4341.09 ; C51.1@3747.5,4341.09 3785.59,4303 3829,4303 3834.9,4297.1 U1.12 ; U1.18@3992.32,4148 3942,4148 3928,4162 3928,4172 v1@4023.18,4267.19 ; U1.31 4078.95,3892.05 v2(4193,3778) ; v2(4017,4320) 4017,4273.37 v1@4023.18,4267.19 ; v2(4062,4302) 4058,4302 v1@4023.18,4267.19 ; C52.1 v1@4023.18,4267.19 ; v2(4131,4735) C17.1 4081.74,4782 v2(4156,4782) ; v2(4157,4825) 4080.74,4825 C1.1 v2(4158,4871) ; v2(4502,4586) 4586,4670 U11.1 ; C39.1 4621.87,4588.24 U11.1 ; v2(4639,3822) 4699.63,3822 C43.1 4706.63,3879.76 U12.1 ; v2(4719,4733) 4719,4710 4679,4670 U11.1 ; v2(5025,4622) 5025,4565.37 C38.1 ; C42.1 5266,3815 v2(5270,3811) ; v2(5142,4771.65) GND1.1
  Bottom Layer w39.37: GND.1 3244.65,4771.65 3289.93,4816.93 U6.1
  other v1: 5078,3082 3189.39,3173.39 3346.87,3173.39 3661.83,3173.39 3819.31,3173.39 3976.79,3173.39 4449.23,3173.39 4606.71,3173.39 4764.19,3173.39 5079.15,3173.39 5236.64,3173.39 3231.91,3215.91 3431.91,3215.91 3631.91,3215.91 3831.91,3215.91 4831.91,3215.91 3189.39,3330.87 3346.87,3330.87 3819.31,3330.87 3976.79,3330.87 5079.15,3330.87 5236.64,3330.87 3231.91,3415.91 3831.91,3415.91 4831.91,3415.91 3324.87,3488.35 3661.83,3488.35 4606.71,3488.35 4764.19,3488.35 5079.15,3488.35 5236.64,3488.35 4503,3539 4185,3567 4723,3608 4606.71,3803.31 5231.91,3815.91 4821.48,3973.91 3661.83,4118.27 4031.91,4215.91 4030.18,4268.14 3504.35,4275.75 3976.79,4275.75 4908.96,4355.14 3431.91,4415.91 3831.91,4415.91 5031.91,4415.91 3346.87,4433.23 3648.91,4432.91 3346.87,4498.8 4593.27,4633.39 3241.87,4693.19 3976.79,4748.19 4750.75,4790.87 3631.91,4815.91 3831.91,4815.91 4835.79,4875.91 3346.87,4905.67 3976.79,4905.67 4134.27,4905.67 4291.75,4905.67 4764.19,4905.67 3231.91,5015.91 3631.91,5015.91 3189.39,5063.15 3346.87,5063.15 5275.64,5129.15
  other v2: 4899,4697
LD1: R32.2 U1.40 | length 479
  Top Layer w10: R32.2 3692,3610 v1(3744,3558)
  Bottom Layer w10: v1(3744,3558) 3775.84,3589.84 U1.40
LD2: R90.2 U1.39 | length 359.3
  Top Layer w10: v1(3873,3610) 3873,3616.37 R90.2
  Bottom Layer w10: U1.39 3794.74,3792.84 3794.74,3752.34 3793.84,3751.44 3793.84,3659.16 3843,3610 v1(3873,3610)
LD3: R91.2 U1.38 | length 890.8
  Top Layer w10: v1(4480,3660) 4521.63,3660 R91.2
  Bottom Layer w10: U1.38 3815.21,3699.79 3874,3641 4464,3641 4480,3657 v1(4480,3660)
LD4: R92.2 U1.37 | length 1500.5
  Top Layer w10: v1(5055,3630) 5125,3700 R92.2
  Bottom Layer w10: U1.37 3834.9,3710.1 3881,3664 4419,3664 4465,3710 4716,3710 4792,3634 5051,3634 v1(5055,3630)
M_SCK: SCK.1 U1.55 | length 695
  Bottom Layer w10: SCK.1 3125.13,3820 3225,3820 3249,3844 3249,4058 3272,4081 3337,4081 3427.53,3990.47 U1.55
M_SDI: SDI.1 U1.57 | length 467.6
  Bottom Layer w10: SDI.1 3336.38,4141.73 3448.27,4029.84 U1.57
M_SDO: SDO.1 U1.56 | length 558
  Bottom Layer w10: SDO.1 3212.25,3984.25 3229,4001 3229,4072 3269,4112 3340.67,4112 3441.72,4010.94 3538.85,4010.94 U1.56
M_SS: SS.1 U1.50 | length 721.6
  Top Layer w10: SS.1 3170.29,3669.29 3274,3773 3475,3773 3615,3913 v1(3615,3933)
  Bottom Layer w10: U1.50 3594.05,3892.05 3615,3913 v1(3615,3933)
RLY: RLY.1 U1.26 | length 1848
  Top Layer w10: v1(4120.5,4300.5) 4071,4350 4071,4417 4158,4504 4881.54,4504 4893.54,4516 4991.46,4516 5012.46,4495 v1(5055,4495)
  Bottom Layer w10: U1.26 4032.87,3990.47 4145,4102.6 4145,4276 v1(4120.5,4300.5) ; v1(5055,4495) 5101,4495 5220.17,4614.17 RLY.1
RST: C46.2 H2.1 R88.1 SW5.1 U1.7 | length 1214.8
  Top Layer w10: H2.1@3319,3748 3348,3719 3466,3719 v2(3639,3892)
  Bottom Layer w10: H2.1@3319,3748 3338,3729 3407.63,3729 C46.2 ; R88.1 C46.2 ; SW5.1 3485.16,3556 3485.16,3626.84 3444,3668 v1(3443,3668) 3443,3693.63 C46.2 ; v2(3639,3892) 3771,4024 3771,4167 3736.47,4201.53 U1.7
SEG_A1: DISP0.11 U11.2 | length 738.4
  Top Layer w10: DISP0.11 4046.88,5055.12 4393,4709 v1(4489,4709)
  Bottom Layer w10: v1(4489,4709) 4565,4709 4576,4720 U11.2
SEG_A2: DISP1.11 U12.2 | length 1091.3
  Bottom Layer w10: DISP1.11 4220,4380.77 4220,4097 4170,4047 4170,3931 4220,3881 4612,3881 4691,3960 U12.2
SEG_B1: DISP0.7 U11.3 | length 517.1
  Top Layer w10: DISP0.7 4424.35,5055.12 4387,5017.76 4387,4826 4452,4761 v1(4542,4761)
  Bottom Layer w10: v1(4542,4761) 4574,4761 4583,4770 U11.3
SEG_B2: DISP1.7 U12.3 | length 633.4
  Bottom Layer w10: DISP1.7 4636.23,4397 4777,4397 4819,4355 4819,4038 4791,4010 U12.3
SEG_C1: DISP0.4 U11.4 | length 586.1
  Bottom Layer w10: DISP0.4 4231.35,4625.35 4480,4874 4527,4874 4581,4820 U11.4
SEG_C2: DISP1.4 U12.4 | length 349.2
  Bottom Layer w10: DISP1.4 4499.23,4060 U12.4
SEG_D1: DISP0.2 U11.5 | length 770.6
  Bottom Layer w10: DISP0.2 4032.35,4556.12 4048.5,4556.12 4422.38,4930 4511,4930 4570,4871 4620.87,4871 U11.5
SEG_D2: DISP1.2 U12.5 | length 724
  Bottom Layer w10: DISP1.2 4217,3977.77 4217,3929 4232,3914 4342,3914 4371,3943 4371,4051 4430,4110 U12.5
SEG_E1: DISP0.1 U11.6 | length 872.3
  Bottom Layer w10: DISP0.1 3987.24,4611 4055,4611 4401,4957 4529,4957 4566,4920 U11.6
SEG_E2: DISP1.1 U12.6 | length 691.5
  Top Layer w10: DISP1.1 4300.23,4161 v1(4443,4161)
  Bottom Layer w10: v1(4443,4161) 4444,4160 U12.6
SEG_F1: DISP0.10 U11.7 | length 775.3
  Top Layer w10: DISP0.10 4192.24,5116 4636,5116 4710,5042 v1(4710,5003)
  Bottom Layer w10: U11.7 4677,4970 v1(4710,5003)
SEG_F2: DISP1.10 U12.7 | length 529.3
  Top Layer w10: DISP1.10 4320.33,4309.67 4418,4212 v1(4450,4212)
  Bottom Layer w10: v1(4450,4212) 4452,4210 U12.7
SEG_G1: DISP0.5 U11.8 | length 616.8
  Top Layer w10: v1(4487,4825) 4543,4881 4543,4995 v1(4549.5,5001.5)
  Bottom Layer w10: DISP0.5 4331.35,4669.35 v1(4487,4825) ; v1(4549.5,5001.5) 4568,5020 U11.8
SEG_G2: DISP1.5 U12.8 | length 464.6
  Top Layer w10: DISP1.5 4520.33,4207.33 v1(4558,4245)
  Bottom Layer w10: v1(4558,4245) 4573,4260 U12.8
SEG_H1: DISP0.3 U11.9 | length 751.4
  Top Layer w10: v1(4430,4880) 4498,4948 v1(4498,5000)
  Bottom Layer w10: DISP0.3 4131.35,4578.35 4430,4877 v1(4430,4880) ; v1(4498,5000) 4498,5003 4565,5070 U11.9
SEG_H2: DISP1.3 U12.9 | length 643.1
  Bottom Layer w10: DISP1.3 4320.33,4135.33 4495,4310 U12.9
SSR: SSR.1 U1.27 | length 1708.2
  Top Layer w10: v1(4173,4303) 4173,4426 4232,4485 4888,4485 4901,4498 4984,4498 v1(5017,4465)
  Bottom Layer w10: U1.27 4040.79,3970.79 4173,4103 v1(4173,4303) ; v1(5017,4465) 5025.31,4456.69 SSR.1
SW1: C3.2 R2.1 SW1.2 U1.41 | length 838.2
  Top Layer w10: SW1.2 3432.77,3370.63 R2.1 ; C3.2 R2.1 ; v1(3692,3565) 3648,3565 3617,3534 3617,3393 3594.63,3370.63 R2.1
  Bottom Layer w10: v1(3692,3565) 3756.16,3629.16 U1.41
SW2: C4.2 R22.1 SW2.2 U1.34 | length 822.6
  Top Layer w10: v1(3965,3759) 3930,3759 3841,3670 3841,3591.18 SW2.2 4061.55,3370.63 R22.1 4111.63,3370 C4.2
  Bottom Layer w10: U1.34 3893.95,3743.05 3909,3728 3934,3728 v1(3965,3759)
SW3: C5.2 R23.1 SW3.1 U1.33 | length 872.8
  Top Layer w10: v1(3993,3793.63) 4062.37,3793.63 4384.11,3471.89 SW3.1 4330.89,3370 R23.1 4266,3369.37 C5.2
  Bottom Layer w10: U1.33 v1(3993,3793.63)
SW4: C6.2 R24.1 SW4.1 U1.28 | length 1626.8
  Top Layer w10: v1(4142,3769) 4599,3312 4893.37,3312 C6.2 R24.1 4966.44,3375.63 SW4.1
  Bottom Layer w10: U1.28 3916.1,3951.1 3893,3928 3893,3883 3941,3835 4076,3835 v1(4142,3769)
SWCLK: H2.4 U1.49 | length 294.9
  Bottom Layer w10: H2.4 3319,4001 3447.64,3872.36 U1.49
SWDIO: H2.2 U1.46 | length 397.5
  Bottom Layer w10: H2.2 3345.25,3848.25 3645.19,3848.25 3658.52,3834.92 3658.52,3794.42 U1.46
U1_EN: U1.61 U1_EN.1 | length 798.8
  Bottom Layer w10: U1_EN.1 3229.83,4614.17 3285,4559 3285,4272 3448.42,4108.58 U1.61
U1_RX: U1.59 U1_RX.1 | length 672.6
  Bottom Layer w10: U1_RX.1 3227.31,4456.69 3263,4421 3263,4266 3459.79,4069.21 U1.59
U1_TX: U1.58 U1_TX.1 | length 524.7
  Bottom Layer w10: U1_TX.1 3204.34,4299.21 3454.03,4049.53 U1.58
U3_RX: U1.30 U3_RX.1 | length 1512.4
  Top Layer w10: v1(4469,3789.26) 4532,3789.26 4636.74,3894 5029,3894 5180,4045 5234,4045 5275.84,4086.84 U3_RX.1
  Bottom Layer w10: U1.30 4109.27,3911.73 4231.74,3789.26 v1(4469,3789.26)
U3_TX: U1.29 U3_TX.1 | length 1597.7
  Top Layer w10: v1(4395,3825) 4452.08,3825 4543.08,3916 5017,3916 5164.54,4063.54 5164.54,4114.9 5164.26,4115.18 5164.26,4176.28 5178.24,4190.26 5179.26,4190.26 5267.84,4278.84 5267.84,4289.21 5275.84,4297.21 U3_TX.1
  Bottom Layer w10: U1.29 4120.58,3931.42 4227,3825 v1(4395,3825)
pads on no net: SW1.1 SW1.3 SW2.1 SW2.3 SW3.2 SW3.4 SW4.2 SW4.4 SW5.2 SW5.4 U1.2 U1.3 U1.4 U1.5 U1.6 U1.8 U1.9 U1.10 U1.11 U1.14 U1.15 U1.16 U1.17 U1.20 U1.21 U1.22 U1.25 U1.42 U1.43 U1.44 U1.45 U1.51 U1.52 U1.53 U1.54 U1.62 U11.10 U11.11 U11.19 U11.20 U12.10 U12.11 U12.19 U12.20

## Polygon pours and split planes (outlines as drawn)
$1N5723 on Bottom Layer (solid, remove dead copper, pour order 2): 3779.5,4742.5 3783,4746 3783,4813 3811,4841 3811,4971.62 3776.62,5006 3747,5006 3717.25,4976.25 3717.25,4850.75 3755,4813 3755,4742.5
GND on Top Layer (solid, remove dead copper, pour order 0): 3030,5215.72 3069.37,5255.09 5352.83,5255.09 5392.2,5215.72 5392.2,3050.37 5352.83,3011 3069.37,3011 3030.37,3050 3030,3050
+5V on Bottom Layer (solid, remove dead copper, pour order 4): 3467,4889 3467,5129 3483,5145 3612,5145 3622,5135 3622,5025 3670.64,4976.36 3670.64,4810.64 3577.95,4717.95 3529.05,4717.95 3492.38,4754.62 3492.38,4863.62
+12V on Bottom Layer (solid, remove dead copper, pour order 6): 3795.27,4795.27 3845,4845 3845,4936.05 3868.95,4960 3932.04,4960 3951,4941.04 3951,4665.81 3925.27,4640.08 3878.92,4640.08 3795.27,4723.73
GND on Bottom Layer (solid, remove dead copper, pour order 8): 3000,5207.72 3039.37,5247.09 5322.83,5247.09 5362.2,5207.72 5362.2,3042.37 5322.83,3003 3039.37,3003 3000,3042.37

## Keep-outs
Board Outline Layer:
  lines w10: 3016,3039.37 ccw(c3055.37,3039.37) 3055.37,3000 5338.83,3000 ccw(c5338.83,3039.37) 5378.2,3039.37 5378.2,5204.72 ccw(c5338.83,5204.72) 5338.83,5244.09 3055.37,5244.09 ccw(c3055.37,5204.72) 3016,5204.72 3016,3039.37

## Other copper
Top Layer:
  drawing of 159 lines, arcs and shapes, not listed
Bottom Layer:
  drawing of 245 lines, arcs and shapes, not listed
